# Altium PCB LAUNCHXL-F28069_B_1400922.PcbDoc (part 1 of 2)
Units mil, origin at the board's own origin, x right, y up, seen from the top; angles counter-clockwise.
Board outline 5140 x 2010 mil, 4 copper layers (Top, GND, VDD, Bottom), stack 60.63 mil thick; 212 components, 173 nets, 714 pads, 424 vias.
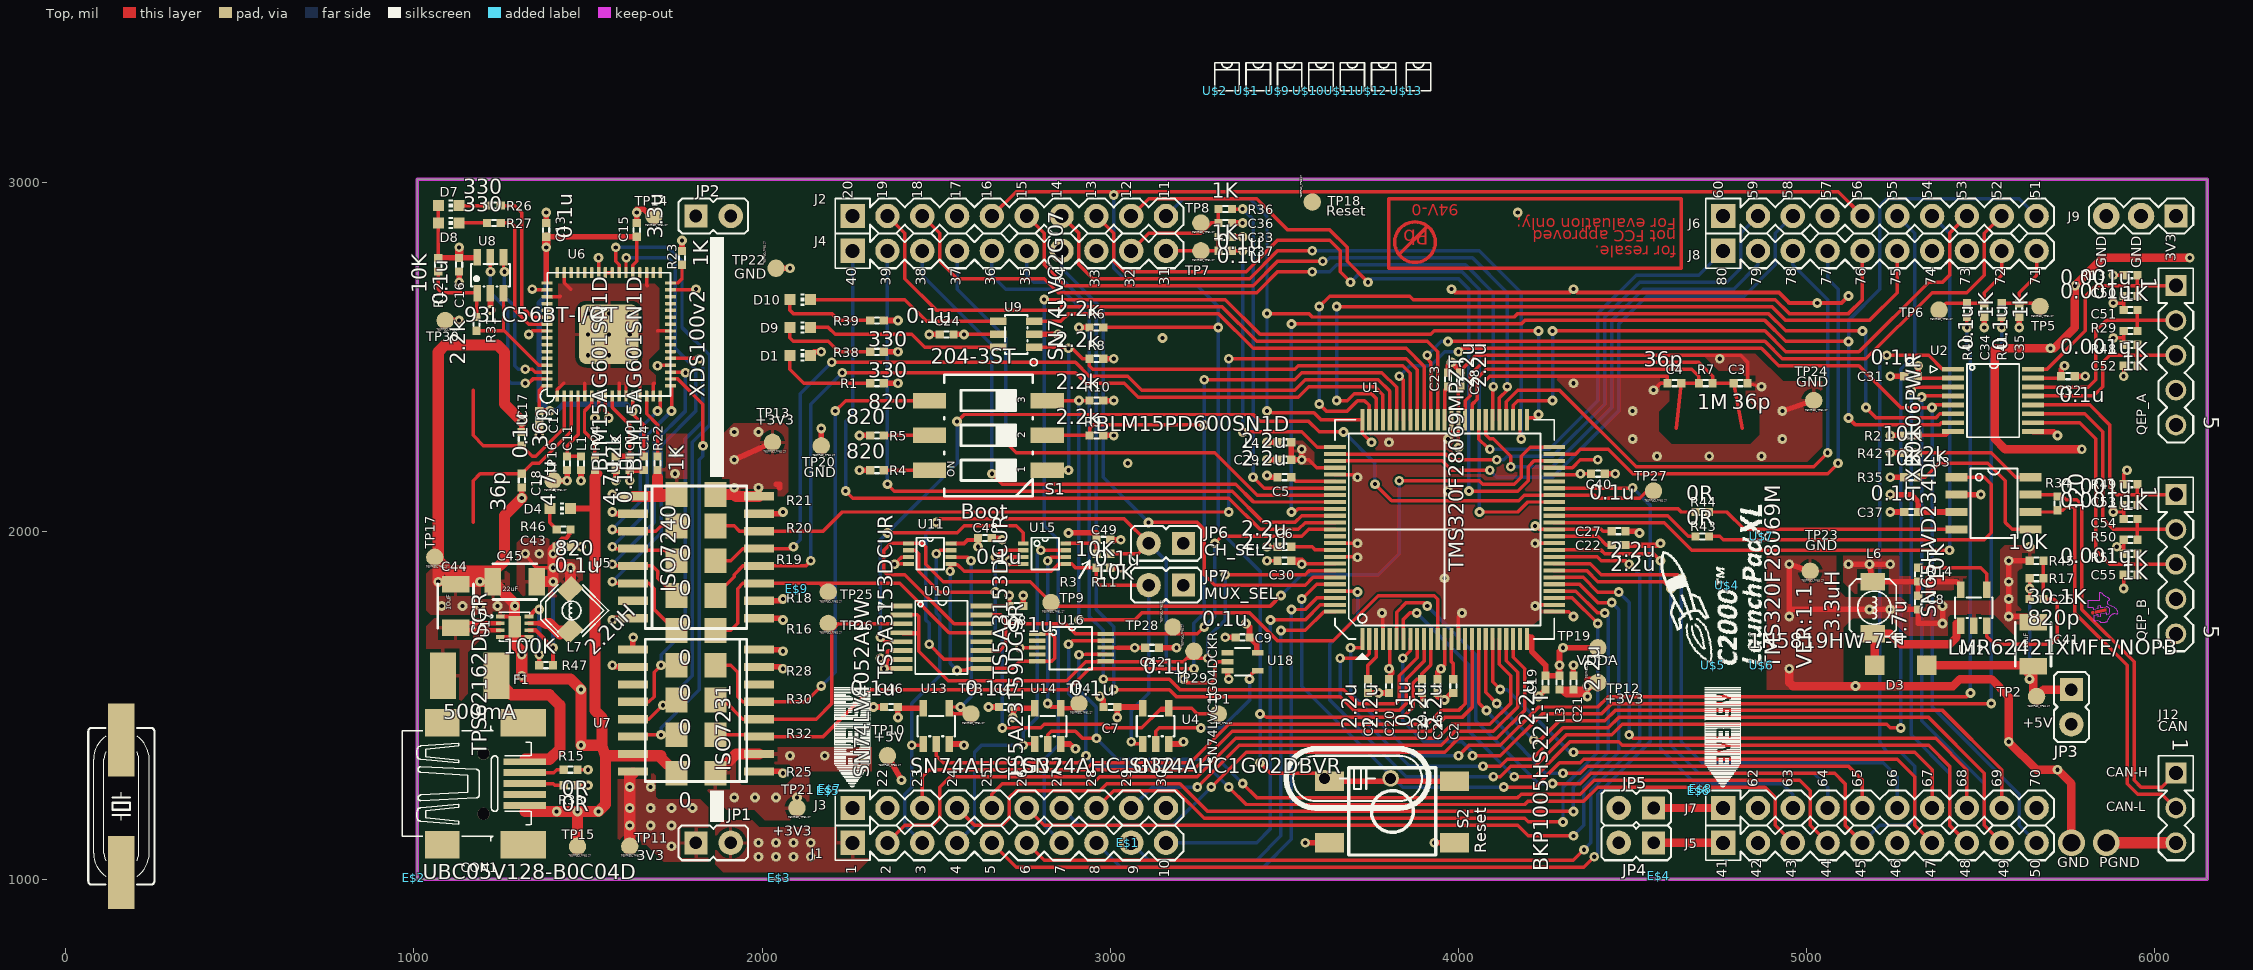
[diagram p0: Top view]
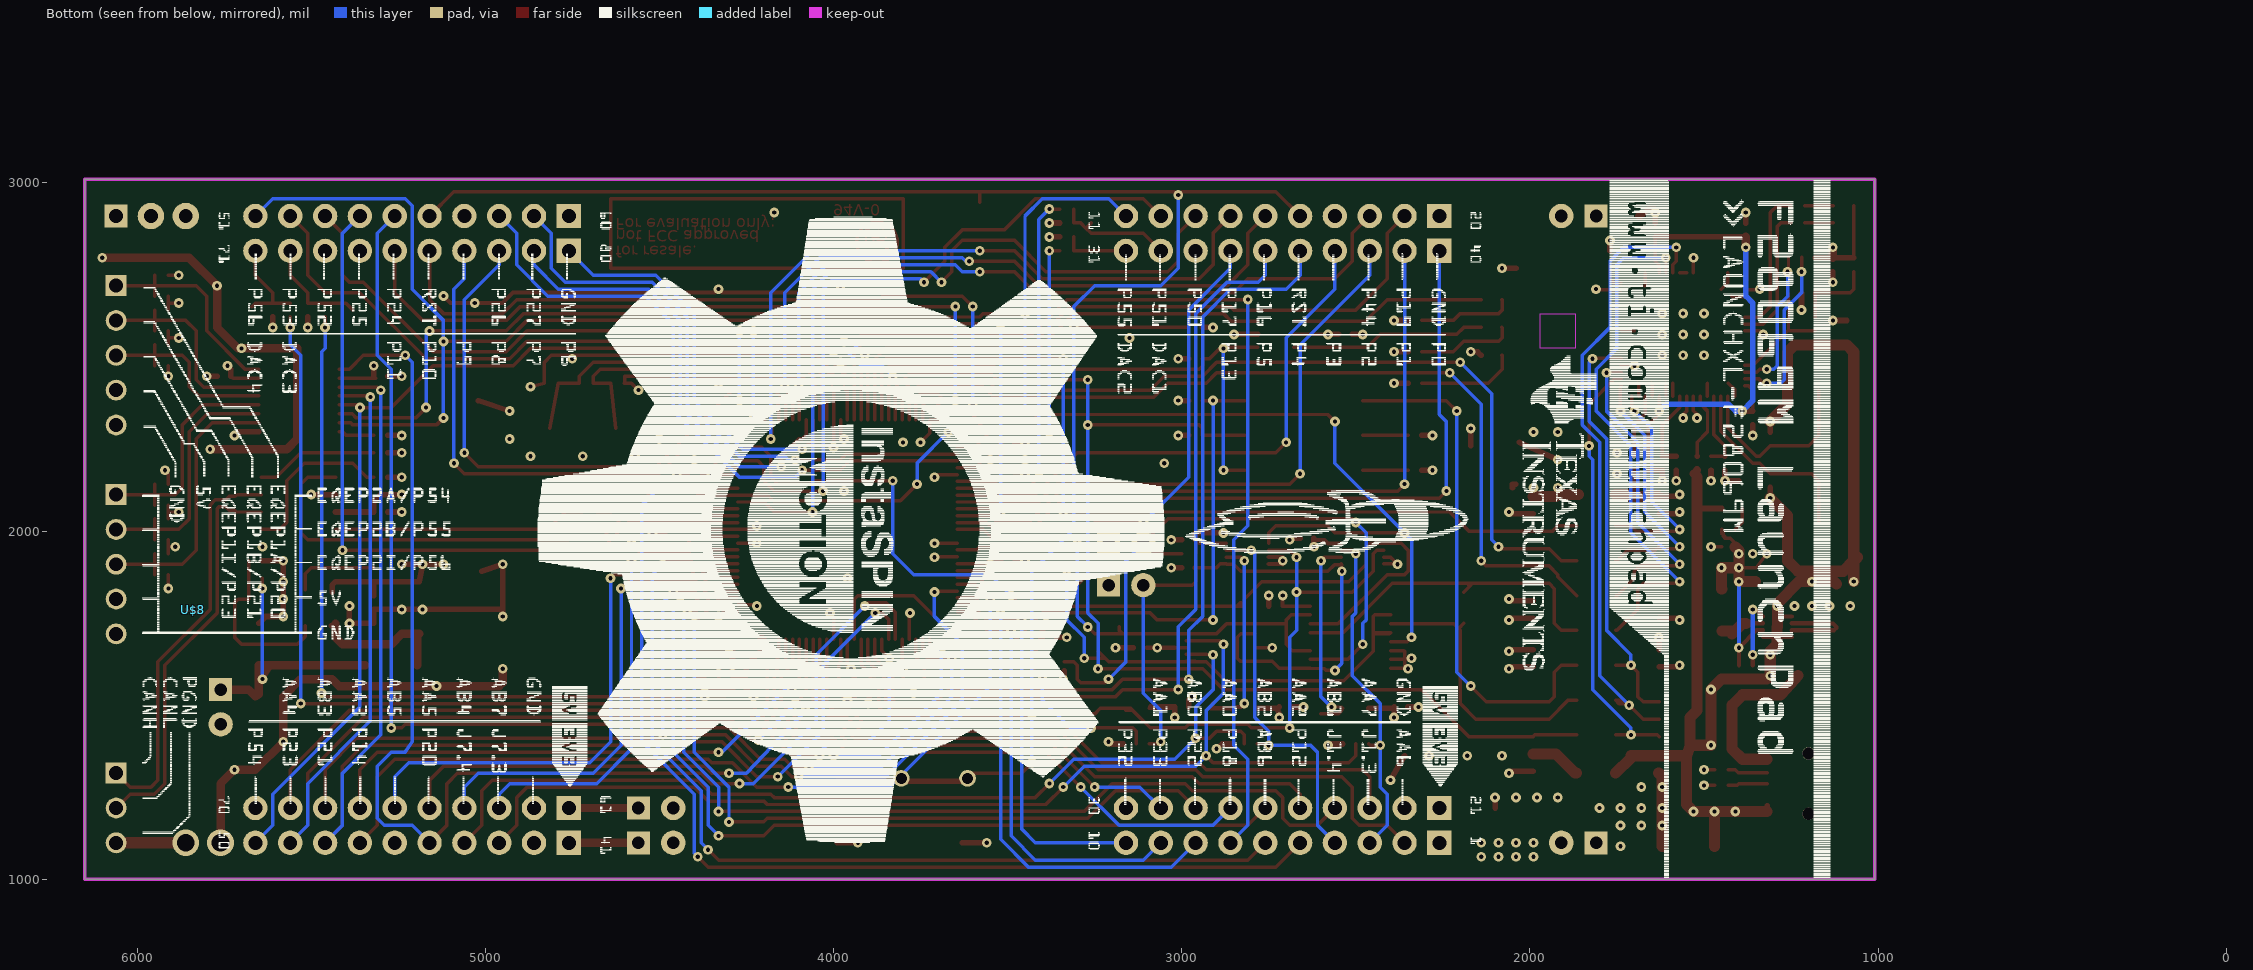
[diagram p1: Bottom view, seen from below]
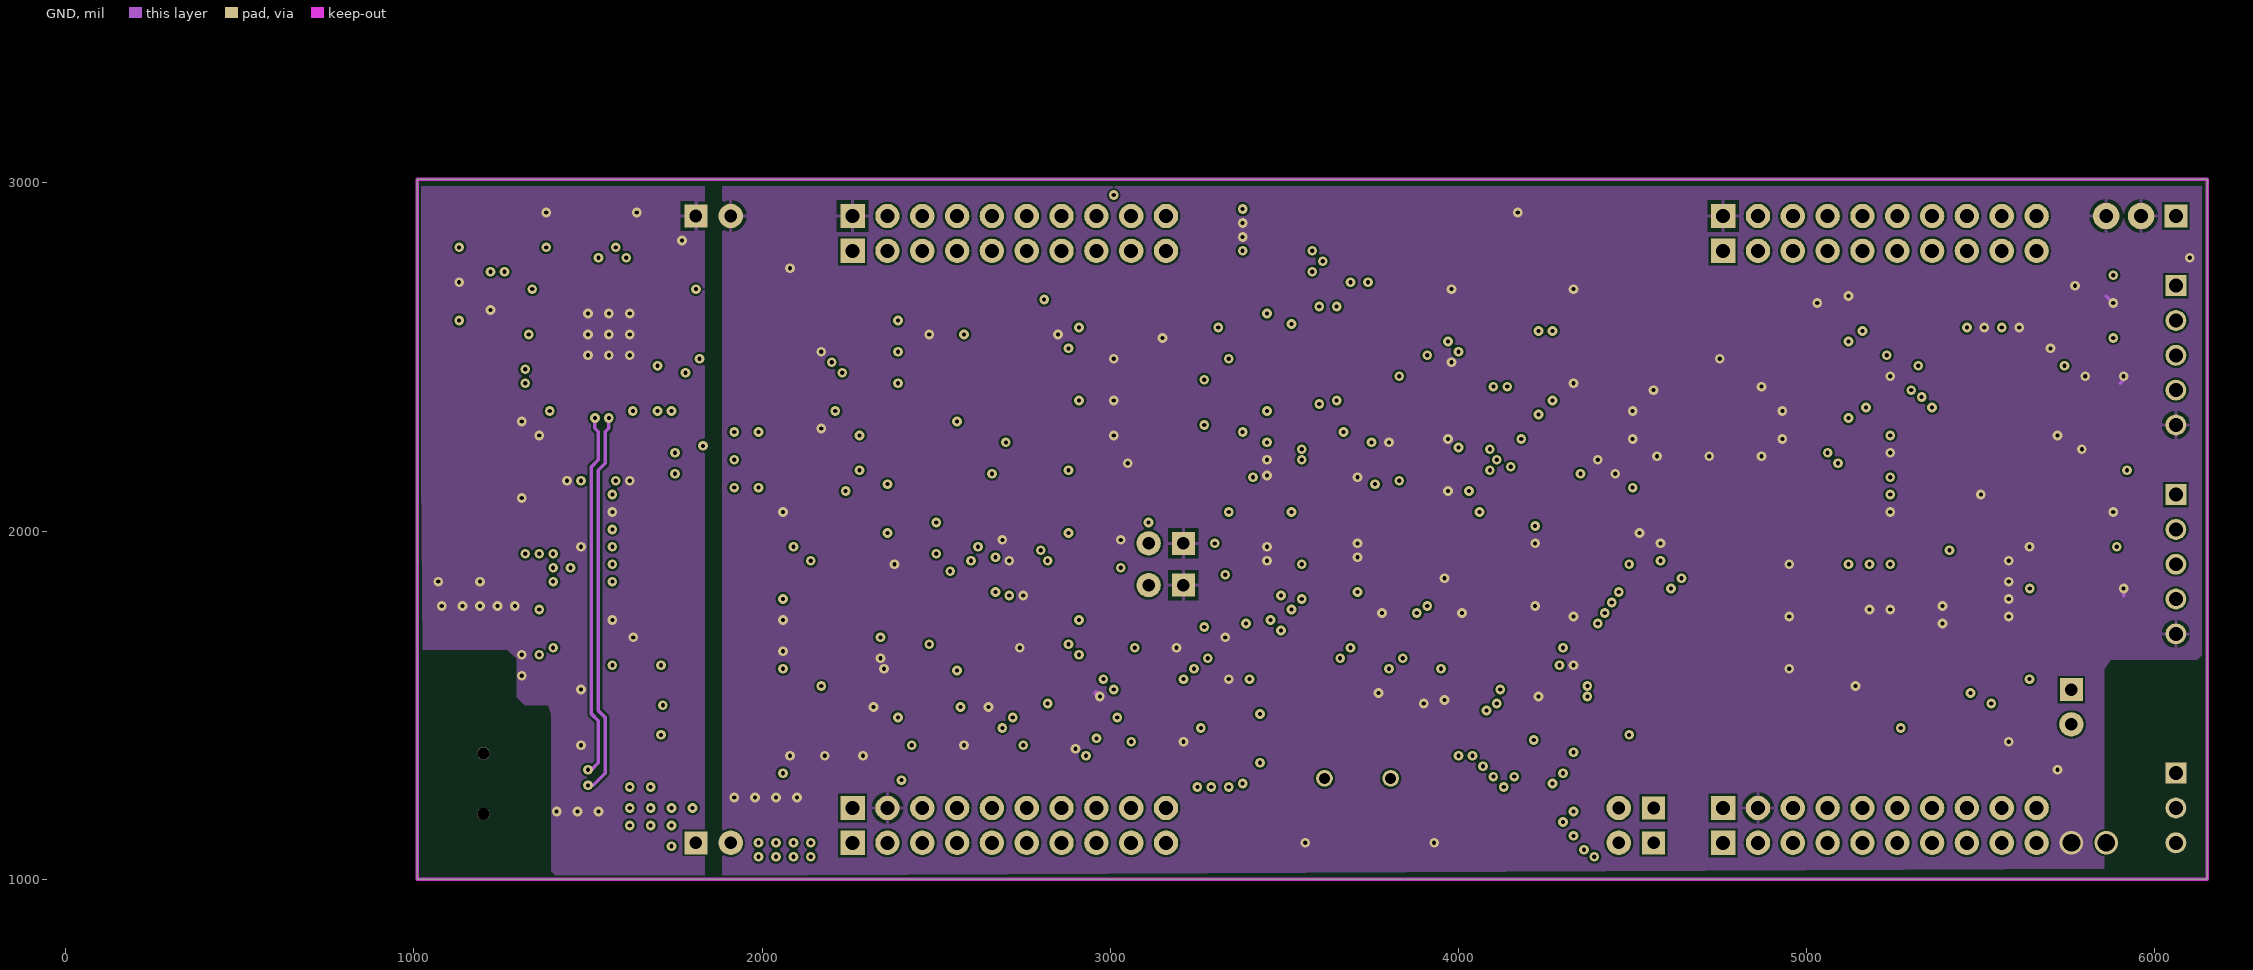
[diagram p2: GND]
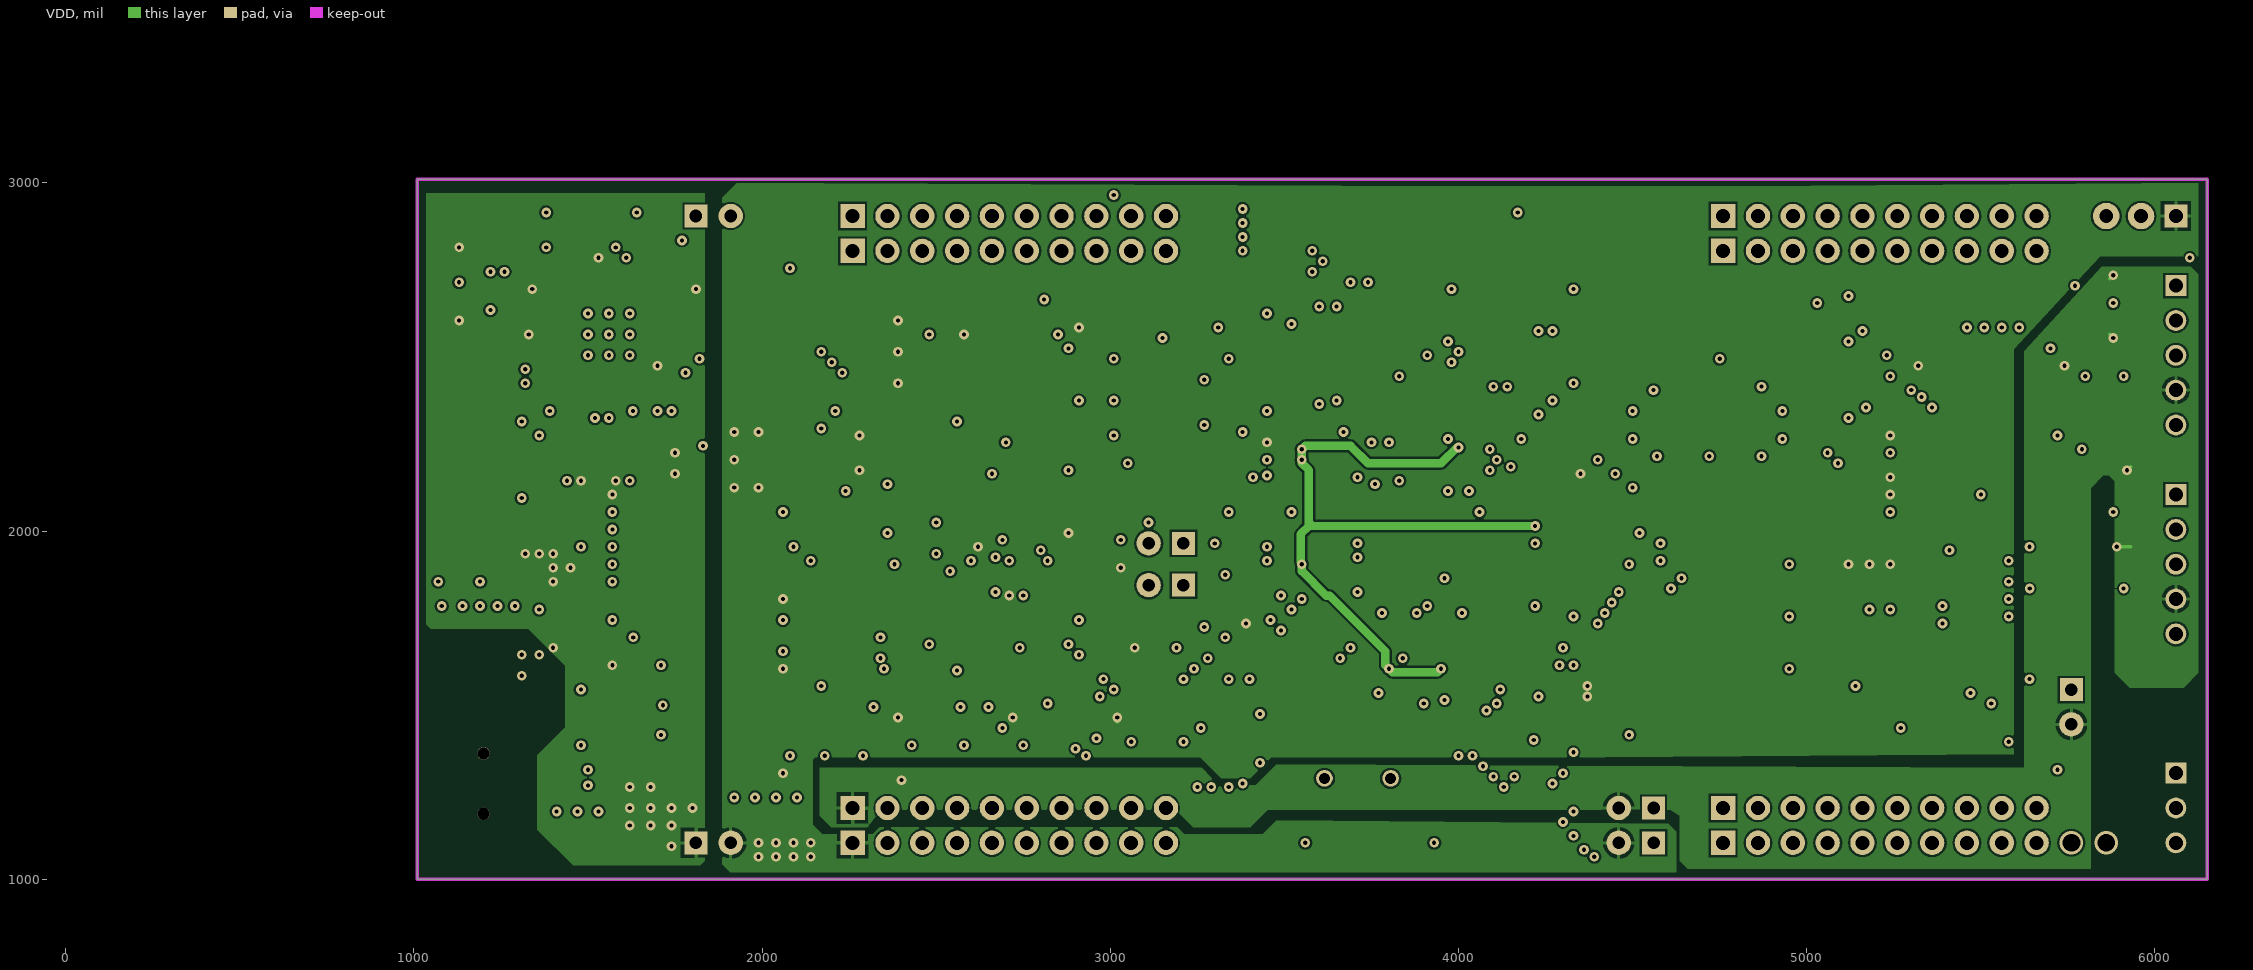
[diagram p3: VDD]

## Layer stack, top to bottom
Top Solder: solder mask 0.4, Solder Resist, Dk 3.5
Top: signal copper 1.378
Dielectric 1: core 11.811, FR-4, Dk 4.8
GND: signal copper 1.378
Dielectric 2: prepreg 11.811, FR-4, Dk 4.8
VDD: signal copper 1.378
Dielectric 3: core 31.4961, FR-4, Dk 4.8
Bottom: signal copper 1.378
Bottom Solder: solder mask 0.4, Solder Resist, Dk 3.5

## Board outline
6150,1000 1010,1000 1010,3010 6150,3010

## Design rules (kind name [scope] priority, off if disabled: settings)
Clearance [All] p1: gap=6 except(0: SMDPad-SMDPad; 5: THPad-THPad THPad-Via; 8: Track-Via Via-Via)
Clearance "Clearance (Same Net)" [All] p2: gap=0 except(5: SMDPad-SMDPad)
HoleSize HoleSize_1 [All] p1: absolutevalues=TRUE maxlimit=100000 minlimit=10 maxpercent=80.000 minpercent=20.000
HoleSize [All] p2: absolutevalues=TRUE maxlimit=100 minlimit=1 maxpercent=80.000 minpercent=20.000
HoleToHoleClearance mdViaViaSameLayer [All] p1: gap=8 allowstackedmicrovias=TRUE
HoleToHoleClearance [All] p2: gap=10 allowstackedmicrovias=TRUE
PasteMaskExpansion mlMinCreamFrame [All] p1: expansion=0
PasteMaskExpansion [All] p2: expansion=0
PolygonConnect ThermalVias [IsVia] p1: connectstyle=Direct reliefconductorwidth=10 reliefentries=4 polygonreliefangle="90 Angle" airgapwidth=10
PolygonConnect [All] p2: connectstyle=Relief reliefconductorwidth=10 reliefentries=4 polygonreliefangle="90 Angle" airgapwidth=10
RoutingVias [All] p1: holewidth=28 width=50 viastyle="Through Hole" minholewidth=28 minwidth=50 maxholewidth=28 maxwidth=50
SilkToSilkClearance [All] p1 off: silktosilkclearance=10
SilkToSolderMaskClearance [IsPad] p1 off: minsilkscreentomaskgap=10 clearancetoexposedcopper=TRUE
SolderMaskExpansion mlMinStopFrame [All] p1: expansion=4
SolderMaskExpansion [All] p2: expansion=4
Width Width_1 [All] p1: maxlimit=100000 minlimit=8 preferedwidth=10
Width [All] p2: maxlimit=10 minlimit=10 preferedwidth=10
25 further rules are at their usual default settings.

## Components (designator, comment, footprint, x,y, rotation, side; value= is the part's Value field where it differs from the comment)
C1 "2.2u" C0402#1 3740,1555 r270 top
C2 "2.2u" C0402#1 3985,1555 r270 top
C3 "36p" C0402#1 4810,2425 r0 top
C4 "36p" C0402#1 4620,2425 r180 top
C5 "2.2u" C0402#1 3500,2155 r180 top
C6 "2.2u" C0402#1 3500,1955 r180 top
C7 "0.1u" C0402#1 3000,1495 r180 top
C8 "4.7u" C0402#1 5320,1795 r270 top
C9 "0.1u" C0402#1 3380,1695 r180 top
C10 "4.7u" C0402#1 1620,2195 r270 top
C11 "4.7u" C0402#1 1440,2195 r270 top
C12 "0.1u" C0402#1 1360,2325 r270 top
C13 "0.1u" C0402#1 1380,2865 r90 top
C14 "0.1u" C0402#1 1660,2195 r270 top
C15 "3.3u" C0402#1 1640,2865 r90 top
C16 "0.1u" C0402#1 1130,2765 r270 top
C17 "36p" C0402#1 1310,2265 r90 top
C18 "36p" C0402#1 1310,2145 r270 top
C19 "2.2u" C0402#1 4250,1565 r270 top
C20 "2.2u" C0402#1 3800,1555 r270 top
C21 "2.2u" C0402#1 4330,1565 r90 top
C22 "2.2u" C0402#1 4460,1960 r0 top
C23 "2.2u" C0402#1 3970,2435 r90 top
C24 "0.1u" C0402#1 2530,2565 r180 top
C25 "820p" C0402#1 5660,1805 r0 top
C26 "2.2u" C0402#1 3940,1555 r270 top
C27 "2.2u" C0402#1 4460,2000 r0 top
C28 "2.2u" C0402#1 4005,2435 r90 top
C29 "2.2u" C0402#1 3500,2205 r180 top
C30 "2.2u" C0402#1 3500,1915 r180 top
C31 "0.1u" C0402#1 5300,2445 r180 top
C32 "0.1u" C0402#1 5750,2445 r0 top
C33 "0.1u" C0402#1 3330,2845 r0 top
C34 "0.1u" C0402#1 5510,2635 r270 top
C35 "0.1u" C0402#1 5610,2635 r270 top
C36 "0.1u" C0402#1 3330,2885 r0 top
C37 "0.1u" C0402#1 5300,2055 r180 top
C38 "0.1u" C0402#1 2730,1785 r0 top
C39 "0.1u" C0402#1 3895,1555 r270 top
C40 "0.1u" C0402#1 4400,2165 r0 top
C41 "10uF" SPARKFUN_1210 5650,1675 r270 top
C42 "0.1u" C0402#1 3120,1665 r0 top
C43 "0.1u" C0402#1 1430,1955 r0 top
C44 "10uF" SPARKFUN_1210 1120,1785 r270 top
C45 "22uF" SPARKFUN_1210 1290,1855 r0 top
C46 "0.1u" C0402#1 2370,1495 r180 top
C47 "0.1u" C0402#1 2700,1495 r180 top
C48 "0.1u" C0402#1 2640,1980 r0 top
C49 "0.1u" C0402#1 2980,1975 r0 top
C50 "0.001u" C0402#1 5930,2675 r180 top
C51 "0.001u" C0402#1 5930,2635 r180 top
C52 "0.001u" C0402#1 5930,2475 r180 top
C53 "0.001u" C0402#1 5930,2075 r180 top
C54 "0.001u" C0402#1 5930,2035 r180 top
C55 "0.001u" C0402#2 5930,1875 r180 top
CON1 "UBC05V128-B0C04D" 32005-201 1200,1275 r0 top
D1 "" CHIP-LED0603 2110,2505 r270 top
D3 "1N5819HW-7-F" SOD123 5270,1615 r180 top
D4 "" CHIP-LED0603 1420,2065 r270 top
D7 "" CHIP-LED0603 1100,2935 r270 top
D8 "" CHIP-LED0603 1100,2885 r270 top
D9 "" CHIP-LED0603 2110,2585 r270 top
D10 "" CHIP-LED0603 2110,2665 r270 top
E$1 "" IS_MOTION 3050,1105 r0 top
E$2 "" F28069M_BACKSILK_1 1000,1005 r0 top
E$3 "" F28069M_BACKSILK_2 2050,1005 r0 top
E$4 "" F28069M_BACKSILK_3 4575,1010 r0 top
E$5 "" POWER_TAG_FRONT 2190,1255 r0 top
E$6 "" POWER_TAG_FRONT 4690,1255 r0 top
E$7 "" POWERTAG_BACK 2195,1260 r0 top
E$8 "" POWERTAG_BACK 4695,1260 r0 top
E$9 "" ROCKET_1 2100,1835 r0 top
F1 "500mA" L1812 1160,1585 r0 top
J1 "" MA10-1 2710,1105 r0 top
J2 "" MA10-1 2710,2905 r0 top
J3 "" MA10-1 2710,1205 r0 top
J4 "" MA10-1 2710,2805 r0 top
J5 "" MA10-1 5210,1105 r0 top
J6 "" MA10-1 5210,2905 r0 top
J7 "" MA10-1 5210,1205 r0 top
J8 "" MA10-1 5210,2805 r0 top
J9 "" CON-LSTB_MA03-1 5960,2905 r180 top
J12 "" MA03-1 6060,1205 r270 top
JP1 "" JP1 1860,1105 r270 top
JP2 "" JP1 1860,2905 r270 top
JP3 "" JP1 5760,1495 r180 top
JP4 "" JP1 4510,1105 r90 top
JP5 "" JP1 4510,1205 r90 top
JP6 "" JP1 3160,1965 r90 top
JP7 "" JP1 3160,1845 r90 top
L1 "BLM15AG601SN1D" R0402 1480,2195 r90 top
L2 "BLM15AG601SN1D" R0402 1580,2195 r90 top
L3 "BKP1005HS221-T" R0402 4290,1565 r270 top
L4 "BLM15PD600SN1D" R0402 3500,2255 r180 top
L6 "3.3uH" INDUCT-3_7*3_5 5190,1855 r270 top
L7 "2.2uH" INDUCT-3.2*3.2 1452.93,1772.07 r45 top
QEP_A "" MA05-1 6060,2505 r270 top
QEP_B "" MA05-1 6060,1905 r270 top
R1 "820" R0402 2330,2425 r0 top
R2 "2.2k" R0402 5300,2275 r0 top
R3 "10K" R0402 2980,1935 r0 top
R4 "820" R0402 2330,2175 r180 top
R5 "820" R0402 2330,2275 r180 top
R6 "2.2k" R0402 2960,2585 r180 top
R7 "1M" R0402 4710,2425 r0 top
R8 "2.2k" R0402 2960,2495 r180 top
R9 "2.2k" R0402 2960,2275 r180 top
R10 "2.2k" R0402 2960,2375 r180 top
R11 "10K" R0402 2980,1895 r180 top
R12 "10K" R0402 1070,2765 r270 top
R13 "1K" R0402 5930,2735 r0 top
R14 "10K" R0402 5320,1875 r90 top
R15 "0R" R0402 1450,1315 r0 top
R16 "0" R1206 1810,1715 r0 top
R17 "30.1K" R0402 5660,1865 r0 top
R18 "0" R1206 1810,1815 r0 top
R19 "0" R1206 1810,1915 r0 top
R20 "0" R1206 1810,2015 r0 top
R21 "0" R1206 1810,2105 r0 top
R22 "1K" R0402 1700,2195 r90 top
R23 "1K" R0402 1770,2785 r90 top
R24 "12k" R0402 1520,2195 r90 top
R25 "0" R1206 1810,1305 r0 top
R26 "330" R0402 1230,2935 r180 top
R27 "330" R0402 1230,2885 r180 top
R28 "0" R1206 1810,1615 r0 top
R29 "1K" R0402 5930,2575 r0 top
R30 "0" R1206 1810,1515 r0 top
R31 "2.2k" R0402 1180,2595 r270 top
R32 "0" R1206 1810,1415 r0 top
R33 "0R" R0402 1450,1270 r0 top
R34 "120" R0402 5720,2080 r90 top
R35 "10K" R0402 5300,2155 r180 top
R36 "1K" R0402 3330,2925 r180 top
R37 "1K" R0402 3330,2805 r180 top
R38 "330" R0402 2330,2515 r0 top
R39 "330" R0402 2330,2605 r0 top
R40 "1K" R0402 5460,2635 r90 top
R41 "1K" R0402 5560,2635 r90 top
R42 "10K" R0402 5300,2225 r180 top
R43 "0R" R0402 4700,1985 r180 top
R44 "0R" R0402 4700,2055 r180 top
R45 "10K" R0402 5660,1915 r180 top
R46 "820" R0402 1430,2005 r0 top
R47 "100K" R0402 1380,1615 r180 top
R48 "1K" R0402 5930,2535 r0 top
R49 "1K" R0402 5930,2135 r0 top
R50 "1K" R0402 5930,1975 r0 top
R51 "1K" R0402 5930,1935 r0 top
S1 "204-3ST" CTS-219-03 2650,2275 r90 top
S2 "" FSMJSMA 3630,1105 r90 top
TP1 "TESTPAD_TPB1,27" TESTPAD_B1,27 3310,1475 r0 top
TP2 "TESTPAD_TPB1,27" TESTPAD_B1,27 5660,1525 r0 top
TP3 "TESTPAD_TPB1,27" TESTPAD_B1,27 2600,1475 r0 top
TP4 "TESTPAD_TPB1,27" TESTPAD_B1,27 2910,1505 r0 top
TP5 "TESTPAD_TPB1,27" TESTPAD_B1,27 5670,2645 r0 top
TP6 "TESTPAD_TPB1,27" TESTPAD_B1,27 5380,2635 r0 top
TP7 "TESTPAD_TPB1,27" TESTPAD_B1,27 3260,2805 r0 top
TP8 "TESTPAD_TPB1,27" TESTPAD_B1,27 3260,2885 r0 top
TP9 "TESTPAD_TPB1,27" TESTPAD_B1,27 2830,1795 r0 top
TP10 "TESTPAD_TPB1,27" TESTPAD_B1,27 2360,1355 r0 top
TP11 "TESTPAD_TPB1,27" TESTPAD_B1,27 1620,1095 r0 top
TP12 "TESTPAD_TPB1,27" TESTPAD_B1,27 4400,1565 r270 top
TP13 "TESTPAD_TPB1,27" TESTPAD_B1,27 2030,2255 r0 top
TP14 "TESTPAD_TPB1,27" TESTPAD_B1,27 1690,2905 r0 top
TP15 "TESTPAD_TPB1,27" TESTPAD_B1,27 1470,1095 r0 top
TP16 "TESTPAD_TPB1,27" TESTPAD_B1,27 1400,2145 r0 top
TP17 "TESTPAD_TPB1,27" TESTPAD_B1,27 1060,1925 r0 top
TP18 "TESTPAD_TPB1,27" TESTPAD_B1,27 3580,2945 r270 top
TP19 "TESTPAD_TPB1,27" TESTPAD_B1,27 4400,1665 r0 top
TP20 "TESTPAD_TPB1,27" TESTPAD_B1,27 2170,2245 r0 top
TP21 "TESTPAD_TPB1,27" TESTPAD_B1,27 2100,1205 r0 top
TP22 "TESTPAD_TPB1,27" TESTPAD_B1,27 2040,2755 r270 top
TP23 "TESTPAD_TPB1,27" TESTPAD_B1,27 5010,1885 r0 top
TP24 "TESTPAD_TPB1,27" TESTPAD_B1,27 5020,2375 r0 top
TP25 "TESTPAD_TPB1,27" TESTPAD_B1,27 2190,1825 r0 top
TP26 "TESTPAD_TPB1,27" TESTPAD_B1,27 2190,1735 r0 top
TP27 "TESTPAD_TPB1,27" TESTPAD_B1,27 4560,2115 r0 top
TP28 "TESTPAD_TPB1,27" TESTPAD_B1,27 3180,1725 r270 top
TP29 "TESTPAD_TPB1,27" TESTPAD_B1,27 3240,1655 r270 top
TP30 "TESTPAD_TPB1,27" TESTPAD_B1,27 1090,2605 r0 top
U1 "TMS320F28069MPZT" PQFP100 3960,2005 r90 top
U2 "TXB0106PWR" TSSOP16-PW 5420,2465 r270 top
U3 "SN65HVD234D" SOIC8-PDSO 5430,2155 r270 top
U4 "SN74AHC1G02DBVR" SOT23-5-DBV 3140,1425 r0 top
U5 "ISO7240" SO-16DW 1810,1925 r270 top
U6 "" QFN64 1560,2565 r90 top
U7 "ISO7231" SO-16DW 1810,1485 r90 top
U8 "93LC56BT-I/OT" SOT23-6 1220,2735 r0 top
U9 "SN74LVC2G07" SOT23-6-DBV 2730,2565 r90 top
U10 "SN74LV4052APW" TSSOP16-PW 2400,1785 r270 top
U11 "TS5A3153DCUR" TI-DCU8 2420,1965 r270 top
U12 "LMR62421XMFE/NOPB" SOT23-5-DBV 5490,1765 r0 top
U13 "SN74AHC1G32" SOT23-5-DBV 2510,1425 r0 top
U14 "SN74AHC1G32" SOT23-5-DBV 2830,1425 r0 top
U15 "TS5A3153DCUR" TI-DCU8 2750,1965 r270 top
U16 "TS5A23159DGSR" TI-DGS10 2790,1705 r270 top
U17 "TPS62162DSGR" TI_DSG8 1250,1755 r270 top
U18 "SN74LVC1G04DCKR" 74XX-LITTLE-DE_SC70-5 3380,1625 r270 top
U$1 "" ROY_JUMPER 3390,3265 r0 top
U$2 "" ROY_JUMPER 3300,3265 r0 top
U$3 "" MSP430_LAB_TILOGO_SMALL 5840,1775 r270 bottom
U$4 "" TRADEMARK 4770,1845 r90 top
U$5 "" STI_LOGO_ROCKET 4730,1615 r90 top
U$6 "" STI_LOGO_LAUNCHPADC2K 4870,1615 r90 top
U$7 "" XL 4870,1985 r90 top
U$8 "" MSP430_LAB_TILOGO_SMALL_TSTOP 5840,1775 r270 bottom
U$9 "" ROY_JUMPER 3480,3265 r0 top
U$10 "" ROY_JUMPER 3570,3265 r0 top
U$11 "" ROY_JUMPER 3660,3265 r0 top
U$12 "" ROY_JUMPER 3750,3265 r0 top
U$13 "" ROY_JUMPER 3850,3265 r0 top

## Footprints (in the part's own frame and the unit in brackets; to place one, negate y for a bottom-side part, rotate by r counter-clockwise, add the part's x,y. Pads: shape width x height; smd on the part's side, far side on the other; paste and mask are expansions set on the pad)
74XX-LITTLE-DE_SC70-5 [mm] "74XX-LITTLE-DE_SC70-5"
  rect 0.4x0.85 smd: 1(-0.65,-1.1) 2(0,-1.1) 3(0.65,-1.1) 4(0.65,1.1) 5(-0.65,1.1)
  silkscreen extent -1,-0.55 1,0.55
32005-201 [mm] "32005-201"
  round 0.9 hole 0.9: 1(0,-2.2) 1(0,2.2)
  rect 3.1x0.5 smd: 1(3,1.6) 2(3,0.8) 3(3,0) 4(3,-0.8) 5(3,-1.6)
  rect 2.5x2 smd: M1(-3,-4.45) M2(-3,4.45)
  rect 3.3x2 smd: M3(2.9,4.45) M4(2.9,-4.45)
  silkscreen extent -5.92,-4.2 3.48,4.2
C0402#1 [mil] "C0402"
  rect 23.62x23.62 smd: 1(-19.69,0) 2(19.69,0)
  silkscreen extent -6,-9 6,9
C0402#2 [mil] "C0402"
  rect 23.62x23.62 smd: 1(-19.69,0) 2(19.69,0)
  round 48 hole 32: 1(2315,585) 2(2125,585)
  rect 76x210 smd: 1(5770,475) 2(5770,855)
  silkscreen extent -6,-9 5865,890
CHIP-LED0603 [mil] "CHIP-LED0603"
  rect 31.5x31.5 smd: A(0,-29.53) C(0,29.53)
  silkscreen extent -18,0 18,12
CON-LSTB_MA03-1 [mil] "CON-LSTB_MA03-1"
  rect 66x66 hole 40: 1(-100,0)
  round 76 hole 40: 2(0,0) 3(100,0)
  silkscreen extent -150,-50 150,50
CTS-219-03 [mil] "CTS-219-03"
  rect 44.49x96.06 smd: 1(-100,-169.29) 2(0,-169.29) 3(100,-169.29) 4(100,169.29) 5(0,169.29) 6(-100,169.29)
  silkscreen extent -175,-127 174,127
F28069M_BACKSILK_1 [mil] "F28069M_BACKSILK_1"
F28069M_BACKSILK_2 [mil] "F28069M_BACKSILK_2"
F28069M_BACKSILK_3 [mil] "F28069M_BACKSILK_3"
FSMJSMA [mil] "FSMJSMA"
  rect 55x83 smd: P$1(0,0) P$2(0,-359) P$3(177,0) P$4(177,-359)
  silkscreen extent -35,-305 215,-55
INDUCT-3.2*3.2 [mil] "INDUCT-3.2*3.2"
  rect 59.06x50 smd: P$1(40.1,46.82) P$2(-44.75,-38.03)
  silkscreen extent -80,-75 75,80
INDUCT-3_7*3_5 [mil] "INDUCT-3_7*3_5"
  rect 50x70.87 smd: P$1(0,0) P$2(150,0)
  silkscreen extent -8,-67 157,67
IS_MOTION [mil] "IS_MOTION"
JP1 [mil] "JP1"
  rect 66x66 hole 36: 1(0,-50)
  round 70 hole 36: 2(0,50)
  silkscreen extent -50,-100 50,100
L1812 [mil] "L1812"
  rect 74.8x133.86 smd: 1(-76.77,0) 2(76.77,0)
MA03-1 [mil] "MA03-1"
  rect 60x60 hole 40: 1(-100,0)
  round 60 hole 40: 2(0,0) 3(100,0)
  silkscreen extent -150,-50 150,50
MA05-1 [mil] "MA05-1"
  rect 60x60 hole 40: 1(-200,0)
  round 60 hole 40: 2(-100,0) 3(0,0) 4(100,0) 5(200,0)
  silkscreen extent -250,-50 250,50
MA10-1 [mil] "MA10-1"
  rect 70x70 hole 40: 1(-450,0)
  round 70 hole 40: 2(-350,0) 3(-250,0) 4(-150,0) 5(-50,0) 6(50,0) 7(150,0) 8(250,0) 9(350,0) 10(450,0)
  silkscreen extent -500,-50 500,50
MSP430_LAB_TILOGO_SMALL [mil] "MSP430_LAB_TILOGO_SMALL"
  Bottom region: 3.06,11.33 -3.71,-19.72 4.8,-19.72 11.79,11.39 3.06,11.28
  Bottom region: 4.42,20.06 5.04,21.29 5.39,21.62 5.71,21.94 6.32,22.24 7.28,22.86 8.94,22.97 10.78,22.89 11.41,22.59 12.08,21.93 12.72,21.26 13,20.96 13.34,20.3 13.66,19.37 13.7,17.47 13.39,16.22 12.68,15.24 11.41,14.23 10.47,13.92 8.75,13.81 7.27,13.96 6.01,14.61 5.35,15.28 4.74,15.93 4.44,16.83 4.3,18.57 4.41,20.06
  Bottom keep-out region: -26.31,31.2 -26.37,20.33 -26.31,9.6 -26.31,-1.13 -45.34,-1.08 -49.02,-1.03 -49.02,-2.87 -48.37,-4.66 -47.45,-6.93 -46.15,-8.56 -44.47,-10.19 -42.63,-12.08 -41.33,-13.33 -40.41,-14.25 -39.43,-15.33 -38.51,-16.8 -37.54,-19.13 -36.56,-21.24 -35.69,-23.25 -34.93,-24.55 -33.41,-26.45 -31.74,-27.69 -31.03,-28.07 -29.35,-28.4 -27.29,-28.07 -26.59,-27.42 -25.88,-26.83 -24.74,-25.47 -23.44,-24.17 -22.52,-23.25 -21.87,-22.98 -19.92,-22.65 -17.97,-22.87 -16.61,-23.85 -15.37,-25.09 -13.2,-29 -11.9,-31.59 -10.98,-33.76 -10.11,-36.04 -8.75,-38.64 -7.51,-41.08 -5.56,-43.95 -3.01,-46.94 -0.79,-48.83 1.54,-50.51 3.17,-51.43 4.74,-52.09 6.26,-52.35 9.08,-52.57 11.03,-52.41 12.44,-52.09 13.31,-51.76 13.96,-51.33 14.12,-50.84 13.63,-49.32 13.04,-47.1 12.65,-44.98 12.44,-43.2 12.6,-41.73 12.98,-39.73 13.63,-38.21 14.23,-36.96 15.26,-35.28 16.5,-33.76 17.8,-32.25 19.16,-30.94 21,-29.37 22.85,-28.02 24.58,-27.1 26.1,-26.18 27.4,-25.53 29.67,-24.28 32.28,-23.25 33.79,-22.54 35.47,-21.95 36.45,-21.52 36.78,-20.97 36.99,-19.72 37.31,-17.78 37.64,-15.44 38.02,-12.03 38.24,-9.81 38.07,-7.85 37.64,-4.66 37.43,-4.39 36.45,-3.79 35.37,-2.98 34.77,-1.84 33.9,-0.11 33.25,2.12 32.87,6.13 33.14,9.7 33.41,11.87 33.25,13.34 32.6,13.66 31.35,13.99 29.46,14.26 27.4,14.53 23.66,14.91 20.3,15.02 16.29,14.96 15.96,13.66 15.37,10.63 14.72,7.86 14.33,6.18 14.12,4.88 21.06,4.88 20.78,3.85 18.83,-4.66 11.9,-4.66 9.19,-17.13 9.13,-19.72 9.51,-20.05 10.11,-20.32 12.76,-20.27 14.61,-20.05 12.76,-27.1 12.11,-28.4 10.22,-28.94 7.99,-29.48 4.8,-30.13 1.81,-30.51 -1.44,-30.19 -2.41,-29.92 -4.2,-29 -5.5,-27.59 -6.53,-26.34 -7.13,-24.77 -7.45,-22.6 -7.4,-19.62 -7.13,-17.99 -5.5,-10.19 -4.47,-5.85 -4.42,-4.66 -11.19,-4.6 -9.08,4.88 -2.09,4.88 0.24,16.26 -1.93,16.48 -3.55,17.13 -4.8,17.78 -4.85,31.22 -26.42,31.28
MSP430_LAB_TILOGO_SMALL_TSTOP [mil] "MSP430_LAB_TILOGO_SMALL_TSTOP"
POWER_TAG_FRONT [mil] "POWER_TAG_FRONT"
  silkscreen extent 17,7 121,299
POWERTAG_BACK [mil] "POWERTAG_BACK"
PQFP100 [mm] "PQFP100"
  rect 1.6x0.3 smd: 1(-8,6) 2(-8,5.5) 3(-8,5) 4(-8,4.5) 5(-8,4) 6(-8,3.5) 7(-8,3) 8(-8,2.5) 9(-8,2) 10(-8,1.5) 11(-8,1) 12(-8,0.5) 13(-8,0) 14(-8,-0.5) 15(-8,-1) 16(-8,-1.5) 17(-8,-2) 18(-8,-2.5) 19(-8,-3) 20(-8,-3.5) 21(-8,-4) 22(-8,-4.5) 23(-8,-5) 24(-8,-5.5) 25(-8,-6) 51(8,-6) 52(8,-5.5) 53(8,-5) 54(8,-4.5) 55(8,-4) 56(8,-3.5) 57(8,-3) 58(8,-2.5) 59(8,-2) 60(8,-1.5) 61(8,-1) 62(8,-0.5) 63(8,0) 64(8,0.5) 65(8,1) 66(8,1.5) 67(8,2) 68(8,2.5) 69(8,3) 70(8,3.5) 71(8,4) 72(8,4.5) 73(8,5) 74(8,5.5) 75(8,6)
  rect 0.3x1.6 smd: 26(-6,-8) 27(-5.5,-8) 28(-5,-8) 29(-4.5,-8) 30(-4,-8) 31(-3.5,-8) 32(-3,-8) 33(-2.5,-8) 34(-2,-8) 35(-1.5,-8) 36(-1,-8) 37(-0.5,-8) 38(0,-8) 39(0.5,-8) 40(1,-8) 41(1.5,-8) 42(2,-8) 43(2.5,-8) 44(3,-8) 45(3.5,-8) 46(4,-8) 47(4.5,-8) 48(5,-8) 49(5.5,-8) 50(6,-8) 76(6,8) 77(5.5,8) 78(5,8) 79(4.5,8) 80(4,8) 81(3.5,8) 82(3,8) 83(2.5,8) 84(2,8) 85(1.5,8) 86(1,8) 87(0.5,8) 88(0,8) 89(-0.5,8) 90(-1,8) 91(-1.5,8) 92(-2,8) 93(-2.5,8) 94(-3,8) 95(-3.5,8) 96(-4,8) 97(-4.5,8) 98(-5,8) 99(-5.5,8) 100(-6,8)
  silkscreen extent -9.5,-8 8,8
QFN64 [mil] "QFN64"
  rrect25% 31.5x9.84 smd: P$1(-177.17,147.64) P$2(-177.17,127.95) P$3(-177.17,108.27) P$4(-177.17,88.58) P$5(-177.17,68.9) P$6(-177.17,49.21) P$7(-177.17,29.53) P$8(-177.17,9.84) P$9(-177.17,-9.84) P$10(-177.17,-29.53) P$11(-177.17,-49.21) P$12(-177.17,-68.9) P$13(-177.17,-88.58) P$14(-177.17,-108.27) P$15(-177.17,-127.95) P$16(-177.17,-147.64) P$33(177.17,-147.64) P$34(177.17,-127.95) P$35(177.17,-108.27) P$36(177.17,-88.58) P$37(177.17,-68.9) P$38(177.17,-49.21) P$39(177.17,-29.53) P$40(177.17,-9.84) P$41(177.17,9.84) P$42(177.17,29.53) P$43(177.17,49.21) P$44(177.17,68.9) P$45(177.17,88.58) P$46(177.17,108.27) P$47(177.17,127.95) P$48(177.17,147.64)
  rrect25% 9.84x31.5 smd: P$17(-147.64,-177.17) P$18(-127.95,-177.17) P$19(-108.27,-177.17) P$20(-88.58,-177.17) P$21(-68.9,-177.17) P$22(-49.21,-177.17) P$23(-29.53,-177.17) P$24(-9.84,-177.17) P$25(9.84,-177.17) P$26(29.53,-177.17) P$27(49.21,-177.17) P$28(68.9,-177.17) P$29(88.58,-177.17) P$30(108.27,-177.17) P$31(127.95,-177.17) P$32(147.64,-177.17) P$49(147.64,177.17) P$50(127.95,177.17) P$51(108.27,177.17) P$52(88.58,177.17) P$53(68.9,177.17) P$54(49.21,177.17) P$55(29.53,177.17) P$56(9.84,177.17) P$57(-9.84,177.17) P$58(-29.53,177.17) P$59(-49.21,177.17) P$60(-68.9,177.17) P$61(-88.58,177.17) P$62(-108.27,177.17) P$63(-127.95,177.17) P$64(-147.64,177.17)
  rrect25% 171.26x171.26 smd: TH(0,0)
  silkscreen extent -197,-177 177,197
R0402 [mil] "R0402"
  rect 23.62x23.62 smd: 1(-19.69,0) 2(19.69,0)
  silkscreen extent -6,-9 6,9
R1206 [mil] "R1206"
  rect 62.99x70.98 smd: 1(-55.98,0) 2(55.98,0)
ROCKET_1 [mil] "ROCKET_1"
ROY_JUMPER [mil] "ROY_JUMPER"
  silkscreen extent 0,0 70,80
SO-16DW [mil] "SO-16DW"
  rect 23.62x86.61 smd: 1(-175,-181.1) 2(-125,-181.1) 3(-75,-181.1) 4(-25,-181.1) 5(25,-181.1) 6(75,-181.1) 7(125,-181.1) 8(175,-181.1) 9(175,181.1) 10(125,181.1) 11(75,181.1) 12(25,181.1) 13(-25,181.1) 14(-75,181.1) 15(-125,181.1) 16(-175,181.1)
  silkscreen extent -204,-146 204,146
SOD123 [mil] "SOD123"
  rect 55.12x55.12 smd: A(74.8,0) C(-74.8,0)
SOIC8-PDSO [mil] "SOIC8-PDSO"
  rect 23.62x62.99 smd: P$1(0,0) P$2(50,0) P$3(100,0) P$4(150,0) P$5(150,212.6) P$6(100,212.6) P$7(50,212.6) P$8(0,212.6)
  silkscreen extent -25,40 175,175
SOT23-5-DBV [mil] "SOT23-5-DBV"
  rect 21.65x47.24 smd: 1(-47.4,-36.18) 2(-10,-36.18) 3(27.4,-36.18) 4(27.4,66.18) 5(-47.4,66.18)
  silkscreen extent -64,-14 44,44
SOT23-6 [mil] "SOT23-6"
  rect 21.65x47.24 smd: 1(-37.4,-51.18) 2(0,-51.18) 3(37.4,-51.18) 4(37.4,51.18) 5(0,51.18) 6(-37.4,51.18)
  silkscreen extent -56,-32 56,32
SOT23-6-DBV [mil] "SOT23-6-DBV"
  rect 21.65x47.24 smd: 1(-37.4,-51.18) 2(0,-51.18) 3(37.4,-51.18) 4(37.4,51.18) 5(0,51.18) 6(-37.4,51.18)
  silkscreen extent -90,-60 56,32
SPARKFUN_1210 [mm] "SPARKFUN_1210"
  rect 1.2x2 smd: 1(-1.6,0) 2(1.6,0)
  silkscreen extent -1.6,-1.3 1.6,1.3
STI_LOGO_LAUNCHPADC2K [mil] "STI_LOGO_LAUNCHPADC2K"
  silkscreen extent 0,0 368,126
STI_LOGO_ROCKET [mil] "STI_LOGO_ROCKET"
  silkscreen extent 3,1 329,149
TESTPAD_B1,27 [mil] "TESTPAD_B1,27"
  rrect100% 50x50 smd: TP(0,0)
TI-DCU8 [mil] "TI-DCU8"
  rect 11.81x31.5 smd: P$1(0,0) P$2(19.69,0) P$3(39.37,0) P$4(59.06,0) P$5(59.06,122.05) P$6(39.37,122.05) P$7(19.69,122.05) P$8(0,122.05)
  silkscreen extent -16,24 75,102
TI-DGS10 [mm] "TI-DGS10"
  rect 0.3x1.2 smd: P$1(0,0) P$2(0.5,0) P$3(1,0) P$4(1.5,0) P$5(2,0) P$6(2,5) P$7(1.5,5) P$8(1,5) P$9(0.5,5) P$10(0,5)
  silkscreen extent -0.5,0.9 2.6,4
TI_DSG8 [mm] "TI_DSG8"
  rect 0.27x0.635 smd: P$1(0,-0.05) P$2(0.5,-0.05) P$3(1,-0.05) P$4(1.5,-0.05) P$5(1.5,2.05) P$6(1,2.05) P$7(0.5,2.05) P$8(0,2.05)
  rect 1.6x0.9 smd: P$9(0.75,1)
  silkscreen extent -0.3,-0.8 1.8,2.1
TRADEMARK [mil] "TRADEMARK"
  silkscreen extent 1,6 52,30
TSSOP16-PW [mm] "TSSOP16-PW"
  rect 0.35x1.6 smd: P$1(0,0) P$2(0.65,0) P$3(1.3,0) P$4(1.95,0) P$5(2.6,0) P$6(3.25,0) P$7(3.9,0) P$8(4.55,0) P$9(4.55,5.85) P$10(3.9,5.85) P$11(3.25,5.85) P$12(2.6,5.85) P$13(1.95,5.85) P$14(1.3,5.85) P$15(0.65,5.85) P$16(0,5.85)
  silkscreen extent -0.38,-1.65 4.95,4.83
XL [mil] "XL"
  silkscreen extent -1,-1 92,61

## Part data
C1 C2 C3 C4 C5 C6 C7 C8 C9 C10 C11 C12 C13 C14 C15 C16 C17 C18 C19 C20 C21 C22 C23 C24 C25 C26 C27 C28 C29 C30 C31 C32 C33 C34 C35 C36 C37 C38 C39 C40 C42 C43 C46 C47 C48 C49 C50 C51 C52 C53 C54 C55: library part C0402
C41 C44 C45: library part SPARKFUN_1210
CON1: library part 32005-201
D1 D4 D7 D8 D9 D10: library part CHIP-LED0603
D3: library part SOD123
E$1: library part IS_MOTION
E$2: library part F28069M_BACKSILK_1
E$3: library part F28069M_BACKSILK_2
E$4: library part F28069M_BACKSILK_3
E$5 E$6: library part POWER_TAG_FRONT
E$7 E$8: library part POWERTAG_BACK
E$9: library part ROCKET_1
F1: library part L1812
J1 J2 J3 J4 J5 J6 J7 J8: library part MA10-1
J9: library part CON-LSTB_MA03-1
J12: library part MA03-1
JP1 JP2 JP3 JP4 JP5 JP6 JP7: library part JP1
L1 L2 L3 L4 R1 R2 R3 R4 R5 R6 R7 R8 R9 R10 R11 R12 R13 R14 R15 R17 R22 R23 R24 R26 R27 R29 R31 R33 R34 R35 R36 R37 R38 R39 R40 R41 R42 R43 R44 R45 R46 R47 R48 R49 R50 R51: library part R0402
L6: library part INDUCT-3_7*3_5
L7: library part INDUCT-3.2*3.2
QEP_A QEP_B: library part MA05-1
R16 R18 R19 R20 R21 R25 R28 R30 R32: library part R1206
S1: library part CTS-219-03
S2: library part FSMJSMA
TP1 TP2 TP3 TP4 TP5 TP6 TP7 TP8 TP9 TP10 TP11 TP12 TP13 TP14 TP15 TP16 TP17 TP18 TP19 TP20 TP21 TP22 TP23 TP24 TP25 TP26 TP27 TP28 TP29 TP30: library part TESTPAD_B1,27
U1: library part PQFP100
U2 U10: library part TSSOP16-PW
U3: library part SOIC8-PDSO
U4 U12 U13 U14: library part SOT23-5-DBV
U5 U7: library part SO-16DW
U6: library part QFN64
U8: library part SOT23-6
U9: library part SOT23-6-DBV
U11 U15: library part TI-DCU8
U16: library part TI-DGS10
U17: library part TI_DSG8
U18: library part 74XX-LITTLE-DE_SC70-5
U$1 U$2 U$9 U$10 U$11 U$12 U$13: library part ROY_JUMPER
U$3: library part MSP430_LAB_TILOGO_SMALL
U$4: library part TRADEMARK
U$5: library part STI_LOGO_ROCKET
U$6: library part STI_LOGO_LAUNCHPADC2K
U$7: library part XL
U$8: library part MSP430_LAB_TILOGO_SMALL_TSTOP

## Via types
v1: diameter 28/28/28/28 (per signal layer), hole 12, Top to Bottom, 422 vias
v2: diameter 76.77/67.18/67.18/76.77 (per signal layer), hole 51.18, Top to Bottom, 2 vias

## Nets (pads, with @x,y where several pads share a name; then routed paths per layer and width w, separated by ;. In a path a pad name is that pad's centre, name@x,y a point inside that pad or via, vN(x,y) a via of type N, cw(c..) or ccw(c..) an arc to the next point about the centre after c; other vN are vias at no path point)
!EN: TP1.TP U4.4 U11.P$2 U15.P$2 | length 1595.3
  Top w10: U11.P$2@2420,1945.31 2439.69,1945.32 2450,1935 2450,1885 2510,1825 v1(2670,1825) ; v1(2670,1925) 2690.32,1945.32 U15.P$2@2750,1945.31 ; v1(2690,1435) 2800,1435 2810,1445 2980,1445 2990,1435 3090,1435 3140,1485 ; U4.4@3161.22,1485 3140,1485 ; TP1.TP@3310,1475 3250,1475 3233.82,1491.18 U4.4@3167.4,1491.18 3146.18,1491.18 3140,1485
  Bottom w10: v1(2670,1925) v1(2670,1825) 2670,1715 2690,1695 v1(2690,1435)
+3V3: C7.1 C8.1 C9.1 C21.1 C24.1 C31.1 C37.1 C38.1 C40.1 C42.1 C46.1 C47.1 C48.1 C49.1 J1.1 J9.1 JP1.2 JP4.2 L3.2 L4.2 L6.P$1 R1.2 R2.1 R3.1 R4.2 R5.2 R6.2 R11.1 R14.1 R21.2 R35.2 R38.2 R39.2 TP12.TP TP13.TP U1.46 U2.P$2 U3.P$3 U4.5 U5.10 U5.16 U7.1 U7.7 U9.5 U10.P$16 U11.P$8 U12.5 U13.5 U14.5 U15.P$8 U16.P$8 U18.5 | length 3222.7
  Top w10: v1(2580,2565) U9.5@2678.82,2565 ; U10.P$16@2630.32,1785 C38.1@2710.31,1785 ; U15.P$8@2872.05,1965 2950,1965 C49.1@2960.31,1975 R3.1@2960.31,1935 ; U16.P$8@2986.85,1665.63 2987.48,1665 3020,1665 ; U4.5@3088.78,1495 U4.5@3092.6,1491.18 ; U1.46@4274.96,2162.48 4347.48,2162.48 v1(4350,2165) ; v1@4348.5,2166.5 v1(4350,2165) ; C40.1@4380.31,2165 v1(4350,2165) ; L6.P$1@5190,1855 L6.P$1@5190.32,1855.32 ; C31.1@5319.69,2445 5314.09,2439.41 U2.P$2@5420,2439.41 ; C8.1@5320,1814.69 C8.1@5320,1815
  Top w12: U11.P$8@2542.05,1965 2580,1965 2590,1975 2615.31,1975 C48.1@2620.31,1980 ; v1(2710,1815) 2710.32,1814.69 C38.1@2710.31,1785 ; 3020,1665 v1(3070,1665) C42.1@3100.31,1665
  Top w16: v1(1920,2205) TP13.TP@2030,2255 ; v1(1990,2125) 1991.1,2123.9 U5.16@1991.1,2100 ; U7.1@1991.1,1310 2055,1310 v1(2060,1305) ; U7.7@1991.1,1610 2055,1610 v1(2060,1605) ; U5.10@1991.1,1800 2055,1800 v1(2060,1805) ; 2040.31,2135.31 2050,2135 2050,2125 ; v1(2280,2175) R4.2@2310.31,2175 ; v1(2280,2275) R5.2@2310.31,2275 ; R1.2@2349.69,2425 v1(2390,2425) ; R38.2@2349.69,2515 v1(2390,2515) ; R39.2@2349.69,2605 v1(2390,2605) ; C46.1@2389.69,1495 C46.1@2390,1494.69 ; v1(2390,1465) C46.1@2390,1494.69 ; U13.5@2462.6,1491.18 C46.1@2393.82,1491.18 ; C24.1@2549.69,2565 v1(2580,2565) ; v1(2620,1955) 2620.31,1955.32 C48.1@2620.31,1980 ; C47.1@2719.69,1495 2723.5,1491.18 C47.1@2726.18,1491.18 ; v1(2720,1465) 2720,1475 C47.1@2726.18,1491.18 ; U14.5@2782.6,1491.18 C47.1@2726.18,1491.18 ; v1(2880,1995) 2960,1995 2960.32,1994.69 C49.1@2960.31,1975 ; v1(2910,2585) R6.2@2940.31,2585 ; R11.1@2999.69,1895 v1(3030,1895) ; v1(3020,1465) 3019.69,1475.32 C7.1@3019.69,1495 U4.5@3088.78,1495 ; v1(3390,1735) 3399.69,1725.32 C9.1@3399.69,1695 3420,1675 3420,1653.9 U18.5@3423.31,1650.59 ; v1(3450,2255) L4.2@3480.31,2255 ; TP12.TP@4390,1575 4370,1575 v1(4370,1555) v1@4370,1545.32 ; TP12.TP@4400,1565 4374.56,1548.13 4370.32,1545.32 v1@4370,1545.32 ; v1(5120,1905) v1(5180,1905) ; v1(5240,1905) v1(5180,1905) ; v1(5240,2105) 5300,2105 5320,2085 5319.69,2084.69 C37.1@5319.69,2055 U3.P$3@5430,2055 ; v1(5240,2155) R35.2@5280.31,2155 ; v1(5240,2275) 5260.32,2275.31 R2.1@5280.31,2275 ; C31.1@5319.69,2445 5319.69,2474.69 v1(5320,2475) ; C8.1@5320,1815 R14.1@5320,1855.31 ; U12.5@5440,1825 5440,1845 5429.69,1855.32 R14.1@5320,1855.31 ; C46.1@2390,1494.69 2393.5,1491.18 C46.1@2393.82,1491.18 ; C46.1@2390,1494.69 2390,1495 C46.1@2393.82,1491.18 ; v1@4370,1545.32 L3.2@4290,1545.31 4310,1530 4360,1530 4360,1535 v1(4370,1525) v1@4370,1545.32 ; v1(5180,1905) L6.P$1@5190,1855 5319.69,1855 R14.1@5320,1855.31
  Top w32: R21.2@1860,2105 R21.2@1865.98,2105 1920,2105 1925,2100 U5.16@1991.1,2100
  VDD w16: v1@3020,1455 v1(3020,1465)
  other v1: 1990,1065 2040,1065 2090,1065 2140,1065 1990,1105 2040,1105 2090,1105 2140,1105 1920,2125 1920,2285 1990,2285
+5V: C32.1 J3.1 JP3.2 JP5.2 QEP_A.4 QEP_B.4 R13.1 R29.1 R48.1 R49.1 R50.1 R51.1 TP10.TP U2.P$15 | length 484.3
  Top w10: U2.P$15@5650.32,2439.41 5724.41,2439.41 5730,2445 C32.1@5730.31,2445 ; v1(5880,2555) 5910.32,2555 ; v1(5880,2735) R13.1@5910.31,2735 ; v1(5890,1955) 5910,1955 5910.32,1954.69 ; R51.1@5910.31,1935 5910.32,1954.69 ; R50.1@5910.31,1975 5910.32,1954.69 ; R49.1@5910.31,2135 5910.32,2165.31 v1(5920,2175) ; R48.1@5910.31,2535 5910.32,2555 ; R29.1@5910.31,2575 5910.32,2555
  Top w16: TP10.TP@2360,1355 v1(2400,1285) ; C32.1@5730.31,2445 5730.32,2464.69 v1(5740,2475)
  VDD w10: 5870,2565 v1(5880,2555) ; 5870,2725 v1(5880,2735) ; v1(5890,1955) 5930,1955 ; v1(5920,2175) 5930,2185
ADCINA0: J3.7 U1.23 | length 1706.2
  Top w10: v1(3290,1265) 3390,1365 3960,1365 4000,1405 4110,1405 4190,1485 4190,1605 4156.85,1638.15 U1.23@4156.85,1690.04
  Bottom w10: J3.7@2860,1205 2910,1155 3180,1155 v1(3290,1265)
ADCINA1: J3.9 U1.22 | length 1438.8
  Top w10: v1(3250,1265) 3370,1385 3950,1385 3990,1425 4100,1425 4170,1495 4170,1595 4137.17,1627.83 U1.22@4137.17,1690.04
  Bottom w10: J3.9@3060,1205 3120,1265 v1(3250,1265)
ADCINA2: J3.5 U1.21 | length 1836.2
  Top w10: J3.5@2660,1205 2660,1245 2690,1275 2950,1275 2970,1295 3250,1295 3360,1405 3940,1405 3980,1445 4090,1445 4150,1505 4150,1585 4117.48,1617.52 U1.21@4117.48,1690.04
ADCINA3: J7.7 U1.20 | length 1599.5
  Top w10: U1.20@4097.8,1690.04 4097.8,1567.2 v1(4120,1545) ; v1(4330,1365) 5310,1365 5360,1315 J7.7@5360,1205
  Bottom w10: v1(4120,1545) 4140,1545 4320,1365 v1(4330,1365)
ADCINA4: J7.9 U1.19 | length 1906.6
  Top w10: U1.19@4078.11,1690.04 4078.11,1536.89 v1(4110,1505) ; v1(4215.85,1400.47) 4235.47,1400.47 4290,1455 4420,1455 4450,1485 5390,1485 5560,1315 J7.9@5560,1205
  Bottom w10: v1(4110,1505) 4204.53,1410.47 v1(4215.85,1400.47)
ADCINA5: J7.5 U1.18 | length 1476.4
  Top w10: U1.18@4058.43,1690.04 4058.43,1506.57 v1(4080,1485) ; v1(4300,1305) 4350,1305 4370,1325 5120,1325 5160,1285 J7.5@5160,1205
  Bottom w10: v1(4080,1485) 4250,1305 v1(4300,1305)
ADCINA6: J1.2 U1.17 | length 2088.8
  Top w10: J1.2@2360,1105 2410,1155 2490,1155 2510,1175 2510,1265 2540,1295 2940,1295 2960,1315 3240,1315 3350,1425 3920,1425 3960,1465 4010,1465 4038.74,1493.74 U1.17@4038.74,1690.04
ADCINA7: J3.3 U1.16 | length 1921.6
  Top w10: J3.3@2460,1205 2460,1295 2480,1315 2930,1315 2950,1335 3230,1335 3340,1445 3910,1445 3950,1485 4000,1485 4019.06,1504.06 U1.16@4019.06,1690.04
ADCINB0: J3.8 U1.28 | length 2164.8
  Top w10: J3.8@2960,1205 3010,1255 3190,1255 3270,1175 4190,1175 4200,1165 v1(4300,1165) ; U1.28@4274.96,1808.15 4326.85,1808.15 v1(4400,1735)
  Bottom w10: v1(4300,1165) 4300,1265 4400,1365 v1(4400,1735)
ADCINB1: J3.4 U1.29 | length 2695.3
  Top w10: J3.4@2560,1205 2610,1155 2690,1155 2710,1175 2710,1235 2730,1255 2970,1255 2990,1275 3200,1275 3280,1195 v1(4330,1195) ; U1.29@4274.96,1827.83 4337.17,1827.83 4400,1765 v1(4420,1765)
  Bottom w10: v1(4330,1195) 4330,1265 4430,1365 4430,1755 v1(4420,1765)
ADCINB2: J3.6 U1.30 | length 2522.1
  Top w10: J3.6@2760,1205 2810,1155 4170,1155 4200,1125 v1(4330,1125) ; U1.30@4274.96,1847.52 4347.48,1847.52 4400,1795 v1(4440,1795)
  Bottom w10: v1(4330,1125) 4360,1155 4360,1265 4460,1365 4460,1775 v1(4440,1795)
ADCINB3: J7.8 U1.31 | length 1746.4
  Top w10: U1.31@4274.96,1867.2 4357.8,1867.2 4400,1825 v1(4460,1825) ; v1(4490,1415) 4500,1405 5370,1405 5460,1315 J7.8@5460,1205
  Bottom w10: v1(4460,1825) 4490,1795 v1(4490,1415)
ADCINB4: J7.4 U1.32 | length 1366.2
  Top w10: U1.32@4274.96,1886.89 4368.11,1886.89 4400,1855 4590,1855 v1(4610,1835)
  Bottom w10: v1(4610,1835) 4610,1385 4690,1305 5020,1305 5060,1265 J7.4@5060,1205
ADCINB5: J7.6 U1.33 | length 1603.7
  Top w10: U1.33@4274.96,1906.57 4378.43,1906.57 4410,1875 4630,1875 v1(4640,1865)
  Bottom w10: v1(4640,1865) 4640,1395 4700,1335 5220,1335 5260,1295 J7.6@5260,1205
ADCINB6: J1.6 U1.34 | length 2755.7
  Top w10: J1.6@2760,1105 2810,1055 4330,1055 v1(4360,1085) ; U1.34@4274.96,1926.26 4398.74,1926.26 4410,1915 4480,1915 v1(4490,1905)
  Bottom w10: v1(4360,1085) 4380,1105 4380,1255 4520,1395 4520,1875 v1(4490,1905)
ADCINB7: J7.3 U1.35 | length 1331.7
  Top w10: U1.35@4274.96,1945.94 4409.06,1945.94 4420,1935 4560,1935 v1(4580,1915)
  Bottom w10: v1(4580,1915) 4580,1375 4680,1275 4930,1275 4960,1245 J7.3@4960,1205
AGND: C10.2 C11.2 C12.2 C13.2 C14.2 C15.2 C16.2 C17.2 C18.2 C43.2 C44.1 C45.1 CON1.5 D4.C JP2.1 R23.2 R24.1 R25.1 TP14.TP TP15.TP TP16.TP TP17.TP U5.2 U5.8 U6.P$1 U6.P$5 U6.P$10 U6.P$11 U6.P$13 U6.P$15 U6.P$25 U6.P$35 U6.P$47 U6.P$51 U6.TH U7.9 U7.15 U8.2 U17.P$1 U17.P$4 U17.P$5 U17.P$9 | length 5179.5
  Top w10: U6.P$51@1382.83,2673.27 1418.27,2673.27 1420,2675 ; U6.P$1@1412.36,2387.83 1412.36,2407.36 1430,2425 ; U6.P$47@1432.05,2742.17 1432.05,2712.95 1450,2695 ; C43.2@1449.69,1955 v1(1480,1955) ; 1490,2425 1491.1,2423.9 U6.P$5@1491.1,2387.83 ; U6.P$10@1589.53,2387.83 1589.53,2424.53 1590,2425 ; U6.P$11@1609.21,2387.83 1609.21,2424.21 1610,2425 ; U7.15@1628.9,1360 U7.15@1633.9,1355 ; U6.P$13@1648.58,2387.83 1648.58,2423.58 1650,2425 ; U6.P$35@1668.27,2742.17 1668.27,2706.73 1670,2705 ; U6.P$15@1687.95,2387.83 1687.95,2422.95 1690,2425 ; 1700,2575 1700.16,2574.84 U6.P$25@1737.17,2574.84 ; R25.1@1754.02,1305 R25.1@1754.02,1310.98
  Top w12: U17.P$4@1248.03,1695.94 1279.06,1695.94 1290,1685 ; U17.P$1@1248.03,1755 1279.37,1755 U17.P$9@1289.37,1745 ; U17.P$9@1290,1695 1290.94,1695.94 U17.P$5@1330.71,1695.94
  Top w16: v1(1130,2715) C16.2@1130,2745.31 ; v1(1220,2635) U8.2@1220,2683.82 ; v1(1310,2095) C18.2@1310,2125.31 ; C17.2@1310,2284.69 v1(1310,2315) ; CON1.5@1318.11,1212.01 1318.11,1196.89 1320,1195 ; v1(1360,2275) C12.2@1360,2305.31 ; C13.2@1380,2884.69 v1(1380,2915) ; TP16.TP@1400,2145 v1(1440,2145) C11.2@1440,2175.31 ; D4.C@1449.53,2065 1510,2065 1520,2075 ; v1(1570,1745) 1575,1750 U5.8@1628.9,1750 ; v1(1570,2055) 1575,2050 U5.2@1628.9,2050 ; v1(1620,2145) C10.2@1620,2175 ; C10.2@1620,2175.31 C10.2@1620,2175 ; U7.9@1628.9,1660 1628.9,1683.9 1630,1685 v1(1630,1695) ; C15.2@1640,2884.69 v1(1640,2915) 1640,2925 1660,2925 1680,2905 TP14.TP@1690,2905 ; C14.2@1660,2175.31 1620.32,2175.31 1620.15,2175.15 C10.2@1620,2175 ; R23.2@1770,2804.69 v1(1770,2835)
  Top w20: R24.1@1520,2175 R24.1@1530,2165
  Top w24: 1520,2155 R24.1@1530,2165 ; R24.1@1520,2175 R24.1@1520,2175.31
  Top w32: TP17.TP@1060,1925 TP17.TP@1070,1915 ; v1(1070,1855) TP17.TP@1070,1915 ; C44.1@1120,1847.99 1127.01,1855 v1(1190,1855) C45.1@1227.01,1855 1289.37,1792.64 1289.37,1745 U17.P$9@1289.37,1725.47 1290,1724.84 1290,1695 1290,1685 1290,1675 1310,1655 v1(1310,1645) v1(1310,1585) 1320,1575 1450,1575 v1(1480,1545) v1(1480,1385) 1540,1385 ; v1(1310,2095) 1260,2045 1260,1915 1230,1885 1100,1885 TP17.TP@1070,1915 ; v1(1310,2315) 1260,2365 1260,2515 1240,2535 1090,2535 1070,2515 TP17.TP@1070,1915 ; 1320,1195 v1(1410,1195) v1(1470,1195) ; TP15.TP@1470,1095 v1(1470,1195) ; 1520,2155 1520,2075 1520,1485 1540,1465 1540,1385 ; R25.1@1754.02,1305 1710,1349.02 1710,1355 1633.9,1355 1550,1355 ; v1(1470,1195) v1(1530,1195) 1550,1215 1550,1355 ; 1540,1385 1550,1355
  other v1: 1080,1785 1140,1785 1190,1785 1240,1785 1290,1785 1500,2505 1560,2505 1620,2505 1500,2565 1560,2565 1620,2565 1500,2625 1560,2625 1620,2625
CANH: J12.1 R34.2 U3.P$7 | length 1155.9
  Top w10: U3.P$7@5642.6,2105 5710,2105 R34.2@5720,2099.69 5735,2100 5744.69,2090.31 5764.69,2090 5775,2090 5790,2075 5790,1775 5940,1625 5940,1285 5960,1265 6020,1265 J12.1@6060,1305
CANL: J12.2 R34.1 U3.P$6 | length 1156.9
  Top w10: U3.P$6@5642.6,2055 5714.69,2055 R34.1@5720,2060.31 5735.32,2060.31 5745,2070 5764.69,2070.31 5770,2065 5770,1765 5920,1615 5920,1275 5950,1245 6020,1245 J12.2@6060,1205
CH_SEL: JP6.2 R3.2 U10.P$10 U18.2 | length 1911.3
  Top w10: v1(2480,1675) 2523.54,1631.46 U10.P$10@2630.32,1631.46 ; v1(2500,2025) 2510,2035 3040,2035 JP6.2@3110,1965 3080,1935 R3.2@2999.69,1935 ; v1(3210,1575) 3220,1565 3290,1565 3300,1575 3300,1615 3310,1625 U18.2@3336.69,1625
  Bottom w10: v1(2480,1675) 2480,1735 2470,1745 2470,1995 v1(2500,2025) ; JP6.2@3110,1965 3160,1915 3160,1625 v1(3210,1575)
D+: R33.2 U6.P$8 | length 1202.6
  Top w10: R33.2@1469.69,1270 v1(1500,1270) ; U6.P$8@1550.16,2387.83 1550.16,2345.16 1550,2345 1560,2335 v1(1560,2325)
  GND w10: v1(1500,1270) 1515,1270 1550,1305 1550,1465 1530,1485 1530,2175 1550,2195 1550,2285 1560,2295 v1(1560,2325)
D-: R15.2 U6.P$7 | length 1146.5
  Top w10: R15.2@1469.69,1315 v1(1500,1315) ; v1(1520,2325) 1520,2335 1530.47,2345.47 U6.P$7@1530.47,2387.83
  GND w10: v1(1500,1315) 1510,1315 1530,1335 1530,1455 1510,1475 1510,2185 1530,2205 1530,2285 1520,2295 v1(1520,2325)
DAC1: C36.1 J4.9 R36.2 TP8.TP | length 344.7
  Top w10: J4.9@3060,2805 3110,2855 3260,2855 TP8.TP@3275,2870 ; TP8.TP@3260,2885 TP8.TP@3275,2870 ; R36.2@3310.31,2925 C36.1@3310.31,2885 3290,2885 TP8.TP@3275,2870
DAC2: C33.1 J4.10 R37.2 TP7.TP | length 190.3
  Top w10: J4.10@3160,2805 TP7.TP@3260,2805 R37.2@3310.31,2805 C33.1@3310.31,2845
DAC3: C34.1 J8.9 R40.2 TP6.TP | length 309.4
  Top w10: TP6.TP@5380,2635 5400,2655 5459.69,2655 R40.2@5460,2654.69 C34.1@5510,2654.69 5510,2685 5560,2735 J8.9@5560,2805
DAC4: C35.1 J8.10 R41.2 TP5.TP | length 285
  Top w10: R41.2@5560,2654.69 C35.1@5610,2654.69 ; J8.10@5660,2805 5660,2735 5610,2685 C35.1@5610,2654.69 ; TP5.TP@5670,2645 5660.32,2654.69 C35.1@5610,2654.69
EQEP1A: C50.1 QEP_A.1 R13.2 U2.P$16 | length 657.8
  Top w10: U2.P$16@5650.32,2465 5690,2465 5800,2575 5800,2675 5830,2705 5950,2705 ; C50.1@5949.69,2675 R13.2@5949.69,2735 5949.69,2705.32 5950,2705 ; QEP_A.1@6060,2705 5950,2705
EQEP1B: C51.1 QEP_A.2 R29.2 U2.P$14 | length 661
  Top w10: U2.P$14@5650.32,2413.82 5808.82,2413.82 5830,2435 5830,2575 5860,2605 5950,2605 ; R29.2@5949.69,2575 C51.1@5949.69,2635 5949.69,2605.31 5950,2605 ; QEP_A.2@6060,2605 5950,2605
EQEP1I: C52.1 QEP_A.3 R48.2 U2.P$13 | length 589.2
  Top w10: U2.P$13@5650.32,2388.23 5823.23,2388.23 5850,2415 5850,2485 5870,2505 5950,2505 ; C52.1@5949.69,2475 R48.2@5949.69,2535 5949.69,2505.31 5950,2505 ; QEP_A.3@6060,2505 5950,2505
EQEP2A: C53.1 QEP_B.1 R49.2 U2.P$12 | length 712
  Top w10: U2.P$12@5650.32,2362.64 5812.36,2362.64 5870,2305 5870,2125 5890,2105 5950,2105 ; R49.2@5949.69,2135 C53.1@5949.69,2075 5949.69,2104.69 5950,2105 ; QEP_B.1@6060,2105 5950,2105
EQEP2B: C54.1 QEP_B.2 R50.2 U2.P$11 | length 783.8
  Top w10: U2.P$11@5650.32,2337.05 5797.95,2337.05 5850,2285 5850,2035 5880,2005 5950,2005 ; R50.2@5949.69,1975 C54.1@5949.69,2035 5949.69,2005.32 5950,2005 ; QEP_B.2@6060,2005 5950,2005
EQEP2I: C55.1@5949.69,1875 QEP_B.3 R51.2 U2.P$10 | length 825.5
  Top w10: U2.P$10@5650.32,2311.46 5783.54,2311.46 5830,2265 5830,1945 5870,1905 5949.69,1905 ; C55.1@5949.69,1875 5949.69,1905 ; R51.2@5949.69,1935 5949.69,1905 ; QEP_B.3@6060,1905 5949.69,1905
FAULT_O: TP3.TP U11.P$6 U13.4 | length 601.4
  Top w10: U13.4@2537.4,1491.18 U13.4@2540,1493.78 ; U11.P$6@2542.05,1925.63 2589.37,1925.63 v1(2600,1915) ; v1(2570,1495) U13.4@2540,1493.78 ; TP3.TP@2600,1475 2550,1475 2540,1485 U13.4@2540,1493.78
  Bottom w10: v1(2570,1495) 2600,1525 v1(2600,1915)
FTDI_1V8: C12.1 C13.1 C14.1 C15.1 U6.P$12 U6.P$37 U6.P$49 U6.P$64 | length 1826.4
  Top w10: C12.1@1360,2344.69 1379.69,2344.69 1380,2345 v1(1390,2345) ; C12.1@1360,2345 1360,2405 1372.36,2417.36 U6.P$64@1382.83,2417.36 ; 1380,2720 1382.83,2722.17 U6.P$49@1382.83,2712.64 ; 1400,2845.32 1400.32,2845 1640,2845 1640,2775 1628.9,2763.9 U6.P$37@1628.9,2742.17 ; U6.P$12@1628.9,2387.83 v1(1628.9,2345) 1628.9,2336.1 1660,2305 C14.1@1660,2214.69
  Top w16: C12.1@1360,2345 v1(1390,2345) ; 1380,2720 v1(1380,2815) ; C13.1@1380,2845.31 1400,2845.32 1470.32,2845.32 1480,2845 1639.69,2845 C15.1@1640,2845.31
  Top w24: v1(1380,2815) C13.1@1380,2845.31
  Bottom w16: v1(1380,2815) 1380,2675 1360,2655 1360,2375 v1(1390,2345) 1410,2345 1430,2365 1608.9,2365 v1(1628.9,2345)
FTDI_3V3: C16.1 C43.1 C45.2 D7.A D8.A JP1.1 L1.1 L2.1 L7.P$1 R12.1 R21.1 R22.1 R46.2 R47.1 TP11.TP TP30.TP U5.1 U6.P$20 U6.P$31 U6.P$42 U6.P$50 U6.P$56 U7.10 U7.16 U8.6 U17.P$6 | length 2051.7
  Top w10: R12.1@1070,2784.69 1070,2884.53 D8.A@1070.47,2885 D7.A@1070.47,2935 ; C16.1@1130,2784.69 C16.1@1130,2785 ; U8.6@1180,2785 1180.32,2784.69 1181.1,2784.69 U8.6@1182.6,2786.18 ; v1(1320,1935) 1350,1895 v1(1400,1895) ; v1(1330,2565) 1339.84,2574.84 U6.P$56@1382.83,2574.84 ; v1(1340,2695) 1342.05,2692.95 U6.P$50@1382.83,2692.95 ; C43.1@1410.31,1955 1410.32,1965.32 1425,1980 1440,1980 1445,1985 1445,1990 ; 1440,1985 1445,1990 ; v1(1530,2785) 1530.47,2784.53 U6.P$42@1530.47,2742.17 ; v1(1700,2475) 1701.42,2476.42 U6.P$20@1737.17,2476.42 ; U6.P$31@1737.17,2692.95 1807.95,2692.95 v1(1810,2695) ; 1445,1990 1449.69,1994.69 R46.2@1449.69,2005 1445,2000.32 1445,1990
  Top w12: U17.P$6@1330.71,1715.63 1349.37,1715.63 v1(1400,1665) ; v1(1400,1665) 1400,1615.32 R47.1@1399.69,1615 1399.69,1654.69 v1(1400,1665)
  Top w16: R12.1@1070,2784.69 C16.1@1130,2784.69 1179.69,2784.69 U8.6@1180,2785 ; TP30.TP@1090,2605 v1(1130,2605) ; v1(1480,2145) L1.1@1480,2175.31 ; v1(1570,1615) 1575,1610 U7.10@1628.9,1610 ; v1(1570,2105) 1575,2100 U5.1@1628.9,2100 ; v1(1580,2145) L2.1@1580,2175.31 ; 1700,2155 R22.1@1700,2175.31
  Top w24: C16.1@1130,2785 v1(1130,2815)
  Top w32: C45.2@1352.99,1855 v1(1400,1855) v1(1400,1895) ; C43.1@1410.31,1955 1400,1944.69 v1(1400,1935) v1(1400,1895) ; L7.P$1@1448.18,1833.53 1450,1833.54 v1(1450,1895) v1(1400,1895) ; TP11.TP@1620,1095 v1(1620,1155) v1(1620,1205) v1(1620,1265) 1620,1295 U7.16@1630,1305 ; U5.1@1628.9,2100 1715,2100 1720,2105 ; 1700,2155 1700,2115 1710,2105 1720,2105 ; R21.1@1754.02,2105 1720,2105
  GND w10: v1@1700,2465 v1(1700,2475)
  Bottom w12: v1(1400,1665) v1(1400,1855)
  other v1: 1740,1095 1680,1155 1740,1155 1680,1205 1740,1205 1800,1205 1680,1265 1360,1935 1750,2165 1750,2225
FTDI_CLK: U6.P$62 U8.4 | length 425.1
  Top w10: U8.4@1257.4,2786.18 1257.4,2747.6 v1(1260,2745) ; v1(1320,2465) 1340,2465 1348.27,2456.73 U6.P$62@1382.83,2456.73
  Bottom w10: v1(1260,2745) 1260,2675 1290,2645 1290,2475 1300,2465 v1(1320,2465)
FTDI_CS: U6.P$63 U8.5 | length 493.9
  Top w10: v1(1220,2745) U8.5@1220,2786.18 ; v1(1320,2425) 1330,2425 1342.05,2437.05 U6.P$63@1382.83,2437.05
  Bottom w10: v1(1220,2745) 1220,2685 1270,2635 1270,2435 1280,2425 v1(1320,2425)
FTDI_DATA: R31.2 U6.P$61 U8.3 | length 353.6
  Top w10: R31.2@1180,2575.31 1190,2575 1260,2575 ; U8.3@1257.4,2683.82 1257.4,2577.6 1260,2575 ; U6.P$61@1382.83,2476.42 1358.58,2476.42 1260,2575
